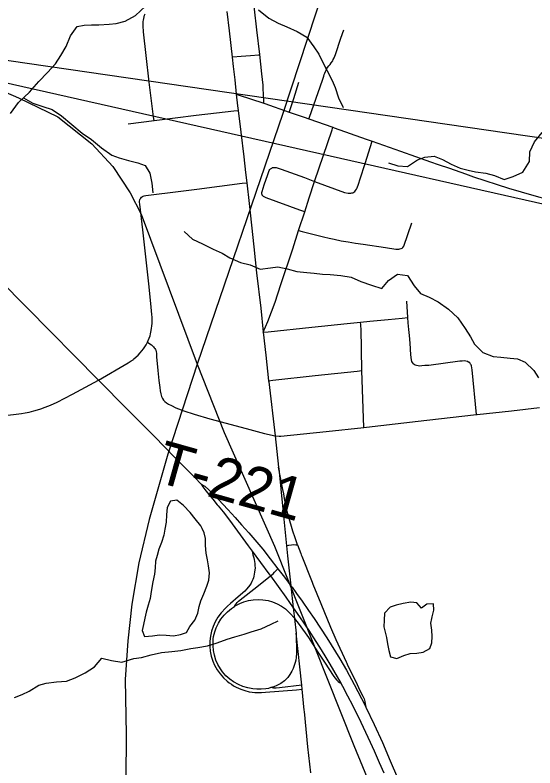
# Model space of a CAD drawing. Extents: x 0 to 34, y -5.4 to 22.
# Drawn here: x 5.887 to 6.58, y 16.492 to 17.496 of the extents above; entities that cross this region are included whole.
import ezdxf

# ---------------------------------------------------------------- set-up
doc = ezdxf.new("R2010")
doc.units = 0
for name, color, linetype in [('GM_X_City_Street', 7, 'Continuous'), ('GM_X_County_Road', 7, 'Continuous'), ('GM_X_Interchange_Ramps', 7, 'Continuous'), ('GM_X_Minor_Lake', 7, 'Continuous'), ('GM_X_Minor_River', 7, 'Continuous'), ('GM_X_Rail_Line', 7, 'Continuous'), ('GM_X_State_Route', 7, 'Continuous'), ('GM_X_Township_Road', 7, 'Continuous'), ('GM_X_Township_Road_Text', 7, 'Continuous'), ('GM_X_US_Route', 7, 'Continuous'), ('SH_Data', 7, 'Continuous')]:
    doc.layers.add(name, color=color, linetype=linetype)

msp = doc.modelspace()

# ---------------------------------------------------------------- linework, layer by layer
at = {"layer": 'GM_X_City_Street'}
for points in [[(6.2188, 17.3787), (6.2188, 17.3805), (6.2184, 17.3908), (6.218, 17.3978), (6.2177, 17.4025), (6.2162, 17.4177), (6.2132, 17.4434), (6.2093, 17.4763), (6.2061, 17.5038), (6.2057, 17.5073), (6.2023, 17.5396), (6.2002, 17.5585), (6.1989, 17.5707), (6.1943, 17.6123), (6.1937, 17.6185), (6.1932, 17.6219), (6.1927, 17.6245), (6.1921, 17.6269), (6.1911, 17.6291)], [(6.0723, 17.3557), (6.0718, 17.3603), (6.066, 17.4066), (6.0618, 17.4422), (6.0584, 17.4737), (6.0577, 17.4818), (6.0577, 17.4849), (6.0578, 17.4874), (6.0581, 17.4895), (6.0585, 17.4917), (6.059, 17.4938), (6.0598, 17.4958), (6.0607, 17.498)], [(6.2788, 17.3576), (6.2798, 17.3602), (6.2971, 17.4095), (6.2978, 17.4118), (6.2986, 17.4147), (6.2993, 17.4167), (6.2999, 17.4185), (6.3008, 17.4207), (6.3018, 17.4228), (6.3029, 17.4248), (6.3037, 17.4262), (6.3055, 17.4285), (6.307, 17.4304), (6.3085, 17.4324), (6.3106, 17.4352), (6.3114, 17.4369), (6.3124, 17.439), (6.3141, 17.4436), (6.3216, 17.4653), (6.3256, 17.4765)], [(6.1766, 17.4402), (6.1775, 17.4403), (6.1887, 17.4413), (6.2009, 17.4423), (6.2121, 17.4433), (6.2132, 17.4434)], [(6.2526, 17.3668), (6.2534, 17.3691), (6.2588, 17.385), (6.2656, 17.4068)], [(6.1819, 17.3907), (6.1845, 17.3898), (6.2188, 17.3787), (6.2199, 17.3783), (6.2526, 17.3668), (6.2725, 17.3598), (6.2788, 17.3576), (6.3108, 17.3465), (6.3124, 17.3459), (6.3551, 17.3308), (6.3632, 17.3278)], [(6.0376, 17.3513), (6.0723, 17.3557), (6.1284, 17.3626), (6.1558, 17.3657), (6.1786, 17.3683), (6.1844, 17.369)], [(6.218, 17.0731), (6.2239, 17.0875), (6.2338, 17.1135), (6.2415, 17.1368), (6.2572, 17.1846), (6.2651, 17.2088), (6.2732, 17.2339), (6.2792, 17.2524), (6.2865, 17.2742), (6.3097, 17.3432), (6.3108, 17.3465)], [(6.3387, 17.2602), (6.3399, 17.261), (6.341, 17.2623), (6.3422, 17.2639), (6.3432, 17.2658), (6.3449, 17.2706), (6.3472, 17.2777), (6.3538, 17.298), (6.3632, 17.3278)], [(6.2732, 17.2339), (6.2669, 17.2362), (6.2218, 17.2526), (6.2201, 17.2533), (6.2184, 17.2542), (6.2173, 17.255), (6.2167, 17.2558), (6.2164, 17.2565), (6.2161, 17.2576), (6.216, 17.2587), (6.2161, 17.2596), (6.2164, 17.2607), (6.2193, 17.2696), (6.224, 17.2836), (6.226, 17.2887), (6.2269, 17.2902), (6.2278, 17.2913), (6.2292, 17.2922), (6.2304, 17.2928)], [(6.2304, 17.2928), (6.2319, 17.293), (6.2334, 17.2931), (6.235, 17.293), (6.242, 17.2906), (6.2728, 17.2794), (6.2865, 17.2742), (6.3265, 17.2595), (6.331, 17.2585), (6.3329, 17.2585), (6.3346, 17.2586), (6.3361, 17.2589), (6.3373, 17.2593), (6.3387, 17.2602)], [(6.0546, 17.2522), (6.0556, 17.2532), (6.0569, 17.254), (6.058, 17.2545), (6.0592, 17.2549), (6.0615, 17.2554), (6.0649, 17.2558), (6.1046, 17.2609), (6.1293, 17.264), (6.19, 17.2718), (6.1961, 17.2726)], [(6.0635, 17.0599), (6.0646, 17.062), (6.066, 17.0654), (6.067, 17.0685), (6.0677, 17.0713), (6.0686, 17.0755), (6.0691, 17.0786), (6.0694, 17.0811), (6.0697, 17.0851), (6.0699, 17.0893), (6.0698, 17.0931), (6.0695, 17.0968), (6.068, 17.1116), (6.0652, 17.1376), (6.0572, 17.2098), (6.0532, 17.2441), (6.0529, 17.2467), (6.053, 17.2482), (6.0533, 17.2498), (6.0538, 17.2509), (6.0546, 17.2522)], [(6.4003, 17.1844), (6.4018, 17.1848), (6.4031, 17.1855), (6.4042, 17.1864), (6.4052, 17.188), (6.4163, 17.219)], [(6.2651, 17.2088), (6.2697, 17.2076), (6.2913, 17.2021), (6.2983, 17.2005), (6.3057, 17.1987), (6.3124, 17.1972), (6.322, 17.1953), (6.331, 17.1936), (6.3409, 17.192), (6.3511, 17.1905), (6.3811, 17.186), (6.3948, 17.1839), (6.3963, 17.1838), (6.3976, 17.1838), (6.3988, 17.184), (6.4003, 17.1844)], [(6.4177, 17.0315), (6.4169, 17.0328), (6.4163, 17.034), (6.4156, 17.0363), (6.4147, 17.0431), (6.4137, 17.0586), (6.4129, 17.069), (6.4123, 17.0767), (6.4114, 17.0859), (6.4108, 17.0928), (6.4092, 17.1148)], [(6.218, 17.0731), (6.2246, 17.0738), (6.2828, 17.08), (6.3299, 17.085), (6.3475, 17.0867), (6.3602, 17.088), (6.3845, 17.0904), (6.403, 17.0921), (6.4108, 17.0928)], [(6.352, 16.9464), (6.3495, 17.0221), (6.3483, 17.078), (6.3482, 17.0807), (6.3479, 17.0832), (6.3475, 17.0867)], [(6.4177, 17.0315), (6.419, 17.0305), (6.4207, 17.0299), (6.4224, 17.0292), (6.4244, 17.0289), (6.4266, 17.0286), (6.4293, 17.0288), (6.4335, 17.0291), (6.4386, 17.0295), (6.4803, 17.035), (6.4831, 17.0353), (6.4859, 17.0355), (6.4883, 17.0353), (6.4901, 17.0347), (6.4922, 17.0334)], [(6.5024, 16.9636), (6.4964, 17.0232), (6.4956, 17.0285), (6.4951, 17.0298), (6.4945, 17.0308), (6.4933, 17.0322), (6.4922, 17.0334)], [(6.225, 17.0084), (6.2307, 17.0091), (6.2872, 17.0155), (6.3432, 17.0214), (6.3495, 17.0221)]]:
    msp.add_lwpolyline(points, dxfattribs=at)
at = {"layer": 'GM_X_County_Road'}
msp.add_line((6.4513, 17.297), (6.4661, 17.2918), dxfattribs=at)
for points in [[(6.3632, 17.3278), (6.4008, 17.3146), (6.441, 17.3005), (6.4513, 17.297)], [(6.4661, 17.2918), (6.4875, 17.2844), (6.4984, 17.2805), (6.5451, 17.2655), (6.5788, 17.2556), (6.6171, 17.2448), (6.6916, 17.2239), (6.7465, 17.208), (6.7901, 17.1955), (6.8302, 17.1847), (6.8367, 17.183)], [(6.2729, 16.5674), (6.2727, 16.5694), (6.2697, 16.5971), (6.2692, 16.6024), (6.2617, 16.6721)], [(6.2815, 16.4857), (6.2776, 16.5205), (6.2729, 16.5674)]]:
    msp.add_lwpolyline(points, dxfattribs=at)
at = {"layer": 'GM_X_Interchange_Ramps'}
for points in [[(6.2638, 16.7897), (6.2604, 16.799), (6.2576, 16.8079), (6.2555, 16.8144), (6.2534, 16.8218), (6.2516, 16.8281), (6.25, 16.8341), (6.2487, 16.8405), (6.2473, 16.8469), (6.2464, 16.8517), (6.2452, 16.8578), (6.2441, 16.8637), (6.2384, 16.8931)], [(6.2031, 16.7814), (6.2034, 16.779), (6.204, 16.7763), (6.2052, 16.7725), (6.2059, 16.7702), (6.2065, 16.7675), (6.2068, 16.7647), (6.2069, 16.7619), (6.207, 16.7591), (6.2065, 16.7535), (6.206, 16.7505), (6.2054, 16.748), (6.2048, 16.7458), (6.2039, 16.7433), (6.2029, 16.7409), (6.2018, 16.7388), (6.2002, 16.7361), (6.1984, 16.7336), (6.1958, 16.7304), (6.1935, 16.7281), (6.1845, 16.7204), (6.1741, 16.7115), (6.1701, 16.7079), (6.1674, 16.7051), (6.162, 16.699), (6.1576, 16.6931), (6.154, 16.6872), (6.1512, 16.681), (6.149, 16.6745), (6.1475, 16.6679), (6.1468, 16.6611), (6.1467, 16.6542), (6.1473, 16.6481), (6.1486, 16.6414), (6.1506, 16.6348), (6.153, 16.6291), (6.1563, 16.6231), (6.1603, 16.6175), (6.1648, 16.6124), (6.1699, 16.6078), (6.1727, 16.6057), (6.1754, 16.6038), (6.1784, 16.6019), (6.1818, 16.6), (6.188, 16.5971), (6.1933, 16.5953), (6.1993, 16.5938), (6.2031, 16.5932), (6.2067, 16.5929), (6.2107, 16.5929), (6.2154, 16.5928), (6.2211, 16.5932), (6.2625, 16.5965), (6.2697, 16.5971)], [(6.1797, 16.7076), (6.181, 16.7099), (6.1821, 16.7115), (6.1832, 16.7128), (6.185, 16.7144), (6.2114, 16.7356), (6.2275, 16.7482), (6.2295, 16.7498), (6.2311, 16.7512), (6.2331, 16.7532), (6.2376, 16.7576)], [(6.2692, 16.6024), (6.2394, 16.5992), (6.235, 16.5988), (6.2318, 16.5987), (6.2282, 16.5993)]]:
    msp.add_lwpolyline(points, dxfattribs=at)
at = {"layer": 'GM_X_Minor_Lake'}
for points in [[(6.1365, 16.8113), (6.1346, 16.815), (6.1271, 16.8243), (6.1204, 16.8327), (6.1115, 16.842), (6.1029, 16.8493), (6.0941, 16.8479), (6.0898, 16.8393), (6.0889, 16.8298), (6.0884, 16.8199), (6.0868, 16.8108), (6.0855, 16.8025), (6.0823, 16.7927), (6.0788, 16.784), (6.0764, 16.7757), (6.0744, 16.7681), (6.0739, 16.759), (6.073, 16.7507), (6.0709, 16.7404), (6.0693, 16.7329), (6.068, 16.7245), (6.0672, 16.7181)], [(6.0672, 16.7181), (6.0644, 16.7094), (6.062, 16.6999), (6.06, 16.692), (6.0583, 16.6837), (6.0567, 16.6757), (6.0596, 16.6673), (6.0702, 16.6683), (6.0797, 16.6697), (6.0884, 16.6691), (6.0983, 16.6686), (6.1078, 16.67), (6.1158, 16.6729), (6.1201, 16.6808), (6.1266, 16.6891), (6.1306, 16.6985), (6.1326, 16.7076), (6.1346, 16.7151), (6.1385, 16.7246), (6.1428, 16.7344), (6.1452, 16.7427), (6.1461, 16.7522), (6.1451, 16.7617), (6.1434, 16.7697), (6.142, 16.7788), (6.141, 16.7887), (6.1408, 16.7982), (6.1393, 16.8058), (6.1365, 16.8113)], [(6.4426, 16.6913), (6.4431, 16.6937), (6.4455, 16.7024), (6.4449, 16.7111), (6.4361, 16.7105), (6.4289, 16.7053), (6.4229, 16.7126), (6.4146, 16.7131), (6.4047, 16.7113), (6.3952, 16.7092), (6.3872, 16.7067), (6.3795, 16.6988), (6.379, 16.6893), (6.3789, 16.6806), (6.3798, 16.6768)], [(6.3798, 16.6768), (6.3824, 16.6661), (6.3838, 16.6577), (6.3852, 16.649), (6.3877, 16.6402), (6.396, 16.6382), (6.4056, 16.6422), (6.4139, 16.6447), (6.4227, 16.6454), (6.431, 16.6464), (6.4402, 16.6515), (6.4426, 16.6591), (6.4431, 16.6675), (6.4428, 16.6758), (6.4415, 16.6853), (6.4426, 16.6913)]]:
    msp.add_lwpolyline(points, dxfattribs=at)
at = {"layer": 'GM_X_Minor_River'}
for points in [[(5.8811, 17.3651), (5.8915, 17.3794), (5.9061, 17.3932), (5.9185, 17.4074), (5.9304, 17.4197), (5.9408, 17.4313), (5.9482, 17.4422), (5.9552, 17.4542), (5.9607, 17.4685), (5.9696, 17.4809), (5.9791, 17.4826), (5.989, 17.4832), (5.9988, 17.4831), (6.0124, 17.484), (6.0219, 17.485), (6.0337, 17.4882), (6.0474, 17.4955), (6.0609, 17.5078)], [(6.2118, 17.503), (6.2256, 17.4918)], [(6.2256, 17.4918), (6.238, 17.4855), (6.2496, 17.4804), (6.2632, 17.4744), (6.2759, 17.4666), (6.2855, 17.4539), (6.2922, 17.444), (6.2969, 17.434), (6.3032, 17.4218), (6.3098, 17.4091), (6.3138, 17.3996), (6.3185, 17.3858), (6.3247, 17.3728)], [(5.8983, 17.3858), (5.9108, 17.3787), (5.924, 17.3743), (5.9364, 17.3703), (5.9491, 17.3617), (5.9629, 17.3501), (5.9764, 17.3385), (5.9891, 17.3303), (6.0022, 17.3191), (6.016, 17.3093), (6.0258, 17.3058), (6.0382, 17.3021), (6.0506, 17.2993), (6.0604, 17.2957), (6.0667, 17.2853), (6.0695, 17.272), (6.0708, 17.2591)], [(6.3848, 17.2993), (6.3976, 17.2949), (6.4101, 17.2943), (6.4238, 17.3032), (6.4334, 17.3065), (6.4459, 17.3082), (6.4568, 17.3034), (6.4684, 17.2972), (6.4804, 17.292), (6.4913, 17.2892), (6.5012, 17.2871), (6.5147, 17.2854), (6.5264, 17.2821), (6.5392, 17.277), (6.5514, 17.281), (6.5643, 17.2868), (6.5729, 17.3011), (6.5735, 17.3136), (6.5798, 17.3272), (6.5898, 17.3395)], [(6.1127, 17.2075), (6.1235, 17.1975), (6.137, 17.1912), (6.1513, 17.1841), (6.163, 17.1786), (6.1734, 17.1723), (6.1874, 17.1664), (6.2005, 17.1632), (6.2137, 17.1572), (6.2277, 17.1593), (6.2372, 17.1603), (6.2497, 17.1578), (6.2628, 17.1541), (6.2761, 17.1528), (6.2859, 17.1522), (6.2968, 17.1505), (6.3074, 17.15), (6.3214, 17.149), (6.335, 17.1465), (6.3481, 17.1409), (6.3624, 17.1358), (6.376, 17.1317), (6.3849, 17.1422), (6.3971, 17.1507), (6.4103, 17.149), (6.4192, 17.1352), (6.4277, 17.1248), (6.439, 17.12), (6.451, 17.1138), (6.4649, 17.104), (6.4775, 17.0924), (6.4871, 17.0782), (6.4941, 17.0671), (6.4997, 17.0575), (6.5108, 17.0463), (6.5244, 17.0408), (6.5346, 17.0399), (6.5474, 17.0385), (6.5572, 17.0376), (6.567, 17.0332), (6.5789, 17.022), (6.5848, 17.0124)], [(5.8861, 16.5863), (5.8964, 16.5903), (5.9059, 16.5947), (5.9185, 16.6024), (5.9284, 16.6053), (5.9421, 16.607), (5.9557, 16.6079), (5.9671, 16.6122), (5.9805, 16.6192), (5.9931, 16.627), (6.0027, 16.6386), (6.0156, 16.6353), (6.0295, 16.6332), (6.0455, 16.6382), (6.0554, 16.6396), (6.0687, 16.6431), (6.0823, 16.646), (6.096, 16.6476), (6.1081, 16.6489), (6.1214, 16.6514), (6.1309, 16.6527), (6.1434, 16.6552), (6.1563, 16.6591), (6.17, 16.6638), (6.1799, 16.6671), (6.1925, 16.6707), (6.202, 16.6739), (6.2153, 16.6779), (6.2283, 16.6841), (6.2378, 16.6885)]]:
    msp.add_lwpolyline(points, dxfattribs=at)
at = {"layer": 'GM_X_Rail_Line'}
for points in [[(8.2982, 20.9), (7.9149, 20.4347), (7.2657, 19.6601), (6.962, 19.2874), (6.9019, 19.2104), (6.8655, 19.1557), (6.8321, 19.1035), (6.789, 19.0121), (6.7581, 18.9233), (6.7239, 18.8129), (6.4727, 18.0601), (6.244, 17.3648), (6.1298, 17.0307)], [(2.1, 19.046), (2.5086, 18.8639), (2.5191, 18.86), (3.2213, 18.5539), (4.0144, 18.2052), (4.7357, 17.8926), (4.9545, 17.7944), (5.8917, 17.3857), (5.944, 17.3605), (5.9893, 17.3246), (6.0173, 17.2941), (6.0405, 17.2593), (6.0551, 17.2305), (6.1298, 17.0307)], [(6.1298, 17.0307), (6.0905, 16.9105), (6.0657, 16.8233), (6.0521, 16.7659), (6.0427, 16.7106), (6.0374, 16.6619), (6.0337, 16.61), (6.035, 16.5368), (6.0346, 16.4766), (6.0418, 16.428), (6.0526, 16.3516), (6.0987, 16.1024), (6.1764, 15.688), (6.2405, 15.3368), (6.3349, 14.8243), (6.4523, 14.2374), (6.4858, 14.1034), (6.4871, 14.1)], [(6.1298, 17.0307), (6.1657, 16.9396), (6.2331, 16.7878), (6.3387, 16.522), (6.5579, 15.9912), (6.6517, 15.7661), (6.8965, 15.1669), (7.1452, 14.5708), (7.2659, 14.2765), (7.3176, 14.1508), (7.3404, 14.1)]]:
    msp.add_lwpolyline(points, dxfattribs=at)
at = {"layer": 'GM_X_State_Route'}
msp.add_line((6.5024, 16.9636), (6.5034, 16.9637), dxfattribs=at)
for points in [[(6.1695, 17.5007), (6.1726, 17.4749), (6.1766, 17.4402)], [(6.1766, 17.4402), (6.178, 17.4277), (6.1799, 17.4097), (6.1819, 17.3907)], [(6.1819, 17.3907), (6.1836, 17.375), (6.1844, 17.369)], [(6.1844, 17.369), (6.1879, 17.3402), (6.1919, 17.3073), (6.1945, 17.2863), (6.1961, 17.2726)], [(6.1961, 17.2726), (6.1993, 17.245), (6.2056, 17.1869), (6.2091, 17.1524), (6.2146, 17.1055), (6.218, 17.0731)], [(6.218, 17.0731), (6.2212, 17.0425), (6.225, 17.0084)], [(6.225, 17.0084), (6.2252, 17.0069), (6.2339, 16.935)], [(6.5034, 16.9637), (6.5491, 16.9685), (6.5862, 16.9727)], [(6.2339, 16.935), (6.2392, 16.9347), (6.2412, 16.9348), (6.3018, 16.9409), (6.352, 16.9464), (6.3632, 16.9476), (6.4363, 16.956), (6.5024, 16.9636)], [(6.2339, 16.935), (6.2384, 16.8931), (6.2386, 16.8917), (6.2441, 16.8373), (6.2491, 16.7885), (6.2505, 16.7749), (6.2547, 16.7351), (6.2579, 16.7059), (6.2595, 16.6917), (6.2617, 16.6721)], [(6.2491, 16.7885), (6.2521, 16.7891), (6.2555, 16.7897), (6.2584, 16.79), (6.2613, 16.7898), (6.2638, 16.7897), (6.2681, 16.778), (6.2687, 16.7762), (6.2695, 16.7744), (6.2821, 16.7421), (6.283, 16.7398), (6.2842, 16.7371), (6.2947, 16.7117), (6.3077, 16.68), (6.3147, 16.6634), (6.3284, 16.6338), (6.3293, 16.6318), (6.33, 16.6305), (6.3431, 16.6035), (6.3449, 16.5997), (6.3473, 16.5948), (6.3508, 16.588), (6.3523, 16.5844), (6.3534, 16.5807), (6.354, 16.5777), (6.3547, 16.5734)], [(6.257, 16.6229), (6.2562, 16.6211), (6.2536, 16.6168), (6.2506, 16.6129), (6.2462, 16.6085), (6.2415, 16.6049), (6.2362, 16.6021), (6.2321, 16.6004), (6.2282, 16.5993), (6.2248, 16.5983), (6.2212, 16.5978), (6.2153, 16.5973), (6.2095, 16.5973), (6.2039, 16.5978), (6.1972, 16.599), (6.1906, 16.601), (6.1849, 16.6035), (6.1784, 16.6071), (6.1733, 16.6107), (6.1682, 16.6152), (6.1637, 16.6204), (6.1608, 16.6244), (6.1573, 16.6303), (6.1549, 16.636), (6.1529, 16.6426), (6.1516, 16.6487), (6.151, 16.6549), (6.151, 16.6605), (6.1513, 16.6643), (6.1517, 16.6673), (6.1524, 16.6707), (6.1534, 16.6739), (6.1552, 16.6792), (6.1582, 16.6853), (6.1615, 16.6906), (6.1658, 16.696), (6.1701, 16.7004), (6.1754, 16.7048), (6.1797, 16.7076), (6.1806, 16.7082), (6.1868, 16.7115), (6.1922, 16.7137), (6.1985, 16.7155), (6.2046, 16.7165), (6.2112, 16.7168), (6.2175, 16.7163), (6.2243, 16.7153), (6.2304, 16.7136), (6.2366, 16.7111), (6.2425, 16.7079), (6.2474, 16.7045), (6.2508, 16.7014), (6.254, 16.6983), (6.2594, 16.6919)], [(6.2596, 16.6916), (6.266, 16.6833), (6.2781, 16.6661), (6.2909, 16.6465), (6.2997, 16.6332), (6.3122, 16.6141), (6.3137, 16.6119), (6.3158, 16.6096), (6.318, 16.6074), (6.3195, 16.6063), (6.3213, 16.6053)], [(6.2617, 16.6721), (6.2621, 16.6456), (6.2618, 16.6394), (6.2613, 16.6358), (6.2606, 16.6327), (6.2589, 16.6273), (6.2578, 16.6247), (6.257, 16.6229)]]:
    msp.add_lwpolyline(points, dxfattribs=at)
at = {"layer": 'GM_X_Township_Road'}
msp.add_line((5.9981, 17.0092), (6.0376, 17.0322), dxfattribs=at)
for points in [[(6.0443, 17.0366), (6.0451, 17.0372), (6.0484, 17.0402), (6.0511, 17.0428), (6.0536, 17.0459), (6.0561, 17.0486), (6.0581, 17.0512), (6.06, 17.0539), (6.0616, 17.0564), (6.0635, 17.0599)], [(6.0635, 17.0599), (6.0668, 17.0579), (6.0691, 17.0562), (6.0708, 17.0547), (6.0718, 17.0536), (6.0727, 17.0526), (6.0735, 17.0515), (6.0741, 17.0502), (6.0745, 17.0491), (6.075, 17.0472), (6.0754, 17.0453), (6.0757, 17.0404), (6.0773, 17.0221), (6.0789, 17.0087), (6.0801, 16.9995), (6.0807, 16.9949), (6.0815, 16.9909), (6.0819, 16.9892), (6.0824, 16.9874)], [(6.0376, 17.0322), (6.0419, 17.0349), (6.0443, 17.0366)], [(5.6524, 16.9373), (5.6783, 16.9401), (5.774, 16.9505), (5.8039, 16.9538), (5.8654, 16.9612), (5.8849, 16.9635), (5.8955, 16.9648), (5.9005, 16.9657), (5.9058, 16.9668), (5.912, 16.9684), (5.9168, 16.9699), (5.9213, 16.9713), (5.927, 16.9732), (5.9343, 16.9761), (5.943, 16.9801), (5.9634, 16.9907), (5.9981, 17.0092)], [(6.0824, 16.9874), (6.0837, 16.9849), (6.0851, 16.9826), (6.0869, 16.9809), (6.089, 16.9791), (6.0914, 16.9775), (6.0954, 16.9754), (6.1015, 16.9725), (6.1119, 16.9686), (6.126, 16.964), (6.1469, 16.9579), (6.175, 16.9503), (6.2002, 16.9435), (6.2147, 16.9395), (6.2198, 16.9381), (6.2339, 16.935)]]:
    msp.add_lwpolyline(points, dxfattribs=at)
at = {"layer": 'GM_X_US_Route'}
for points in [[(5.4298, 17.5482), (5.4613, 17.524), (5.505, 17.4894), (5.5409, 17.4599), (5.5696, 17.4351), (5.5941, 17.4136), (5.6225, 17.387), (5.6504, 17.3599), (5.6803, 17.3308), (5.7921, 17.2178), (5.9025, 17.1063), (5.9981, 17.0092), (6.0363, 16.9707), (6.0631, 16.9439), (6.0729, 16.934)], [(6.0729, 16.934), (6.1002, 16.9062), (6.1265, 16.8794), (6.1353, 16.8707)], [(6.1353, 16.8707), (6.1376, 16.867), (6.14, 16.8635), (6.1456, 16.8568), (6.1506, 16.8506), (6.1567, 16.8432)], [(6.1353, 16.8707), (6.1401, 16.8681), (6.1453, 16.8632), (6.1581, 16.8503), (6.1707, 16.8368), (6.1806, 16.8264), (6.1891, 16.8166), (6.1987, 16.8057), (6.2172, 16.7838), (6.2272, 16.7712), (6.2376, 16.7576), (6.2462, 16.7464), (6.2547, 16.7351), (6.2563, 16.7332), (6.2624, 16.7247), (6.2698, 16.7146), (6.2785, 16.702), (6.2857, 16.6917), (6.3026, 16.6656), (6.32, 16.6377), (6.3288, 16.6227), (6.3393, 16.6036), (6.3537, 16.5754), (6.3547, 16.5734), (6.3659, 16.5503), (6.3769, 16.526), (6.3872, 16.5019), (6.3969, 16.4792)], [(6.1567, 16.8432), (6.158, 16.8417), (6.1645, 16.8338), (6.1701, 16.8263), (6.1766, 16.8176), (6.1978, 16.7885), (6.2031, 16.7814), (6.2255, 16.751), (6.2275, 16.7482), (6.2481, 16.7198), (6.2579, 16.7059), (6.2663, 16.6939), (6.2796, 16.6743), (6.2842, 16.667), (6.2931, 16.6534), (6.3, 16.6417), (6.3069, 16.6306), (6.3213, 16.6053), (6.3237, 16.6011), (6.3305, 16.5882), (6.3368, 16.5759), (6.3482, 16.5531), (6.3606, 16.5267), (6.3657, 16.5151), (6.3725, 16.4994), (6.3786, 16.4855)]]:
    msp.add_lwpolyline(points, dxfattribs=at)
at = {"layer": 'SH_Data'}
msp.add_lwpolyline([(9.2327, 16.948), (5.505, 17.4894), (9.2327, 16.6485)], close=True, dxfattribs=at)

# ---------------------------------------------------------------- texts
at = {"layer": 'GM_X_Township_Road_Text'}
msp.add_text('T-221', height=0.05682, rotation=344.2616, dxfattribs=at).set_placement((6.0719, 16.8747))

doc.saveas('drawing.dxf')
